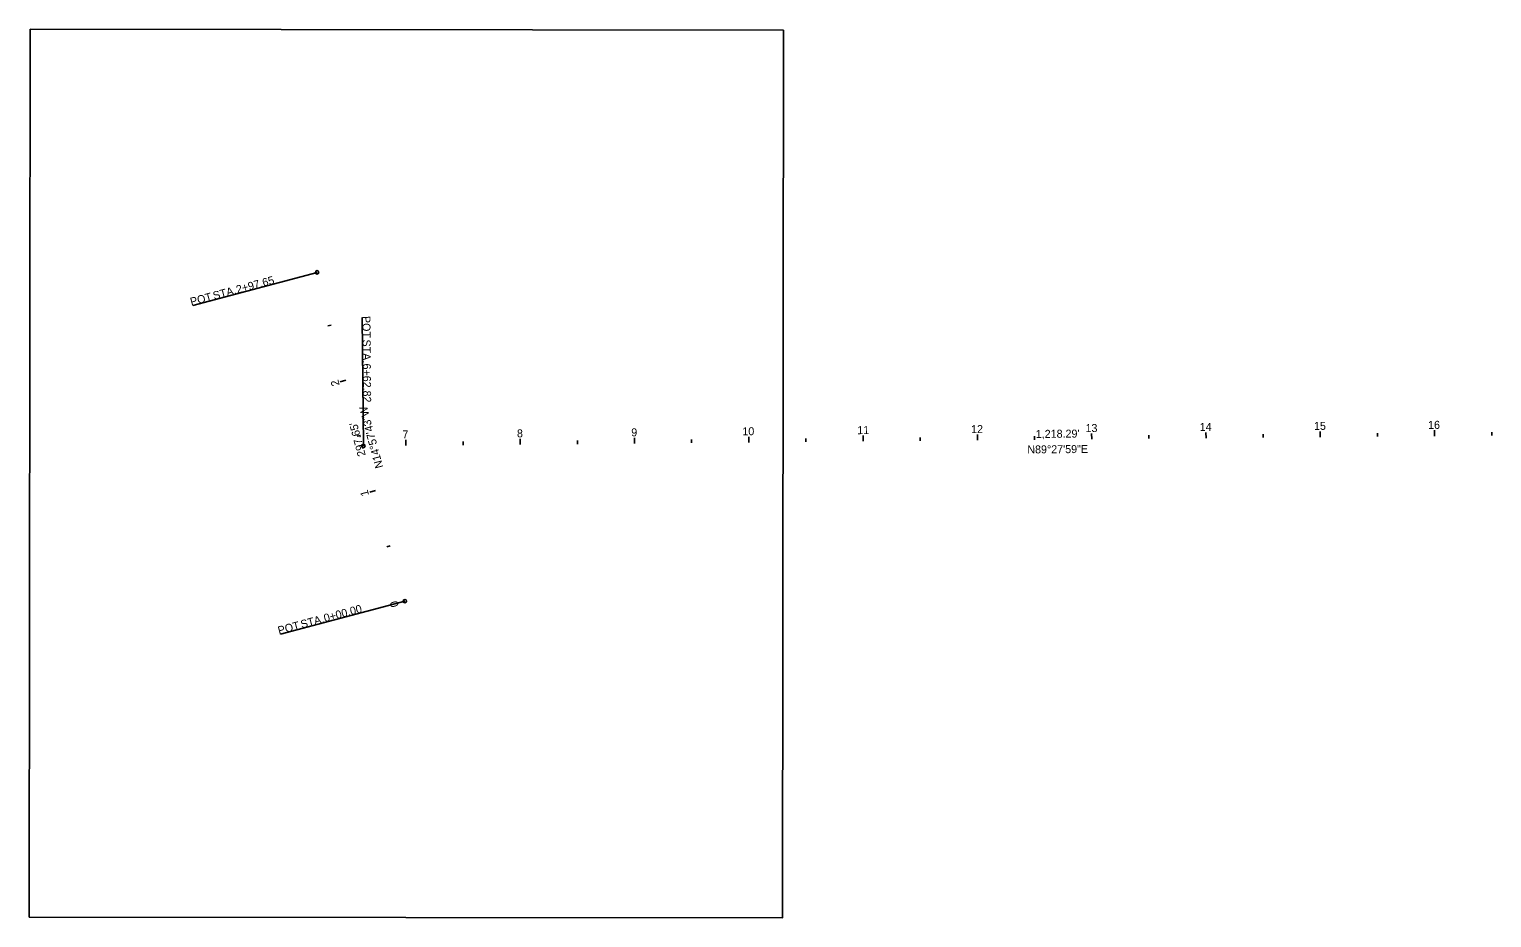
# Model space of a CAD drawing. Extents: x 1805035 to 1810276, y 297762 to 303660.
# Drawn here: x 1805035 to 1806314, y 297921 to 298699 of the extents above; entities that cross this region are included whole.
import ezdxf

# ---------------------------------------------------------------- set-up
doc = ezdxf.new("R2010")
doc.units = 0
for name, color, linetype in [('GE_P_Alignment_100_Bearings', 7, 'Continuous'), ('GE_P_Alignment_100_Cardinal_Points', 7, 'Continuous'), ('GE_P_Alignment_100_Distances', 7, 'Continuous'), ('GE_P_Alignment_100_Stations', 7, 'Continuous'), ('SH_Data', 7, 'Continuous')]:
    doc.layers.add(name, color=color, linetype=linetype)

msp = doc.modelspace()

# ---------------------------------------------------------------- linework, layer by layer
at = {"layer": 'GE_P_Alignment_100_Cardinal_Points'}
for p, q in [((1805286.6, 298486), (1805177.9, 298456.9)), ((1805327.1, 298334.1), (1805326.1, 298446.6)), ((1805363.4, 298198.4), (1805254.7, 298169.4))]:
    msp.add_line(p, q, dxfattribs=at)
for centre in [(1805286.6, 298486), (1805327.1, 298334.1), (1805363.4, 298198.4)]:
    msp.add_circle(centre, 1.5, dxfattribs=at)
at = {"layer": 'GE_P_Alignment_100_Stations'}
for p, q in [((1805298.9, 298439.9), (1805296, 298439.2)), ((1805311.8, 298391.6), (1805306.9, 298390.3)), ((1805324.7, 298343.3), (1805321.8, 298342.6)), ((1805664.3, 298337.2), (1805664.3, 298342.2)), ((1805764.3, 298338.2), (1805764.3, 298343.2)), ((1805814.3, 298338.6), (1805814.3, 298341.6)), ((1805864.3, 298339.1), (1805864.3, 298344.1)), ((1805914.3, 298339.6), (1805914.3, 298342.6)), ((1805964.3, 298340), (1805964.2, 298345)), ((1806014.3, 298340.5), (1806014.3, 298343.5)), ((1806064.3, 298341), (1806064.2, 298346)), ((1806114.3, 298341.4), (1806114.3, 298344.4)), ((1806164.3, 298341.9), (1806164.2, 298346.9)), ((1806214.3, 298342.4), (1806214.3, 298345.4)), ((1806264.3, 298342.8), (1806264.2, 298347.8)), ((1806314.3, 298343.3), (1806314.3, 298346.3)), ((1805364.3, 298334.4), (1805364.3, 298339.4)), ((1805414.3, 298334.9), (1805414.3, 298337.9)), ((1805464.3, 298335.4), (1805464.3, 298340.4)), ((1805514.3, 298335.8), (1805514.3, 298338.8)), ((1805564.3, 298336.3), (1805564.3, 298341.3)), ((1805614.3, 298336.8), (1805614.3, 298339.8)), ((1805714.3, 298337.7), (1805714.3, 298340.7)), ((1805337.6, 298295), (1805332.8, 298293.7)), ((1805350.5, 298246.7), (1805347.6, 298245.9)), ((1805363.4, 298198.4), (1805358.6, 298197.1))]:
    msp.add_line(p, q, dxfattribs=at)
at = {"layer": 'SH_Data'}
msp.add_lwpolyline([(1805694.7, 298698), (1805693.9, 297921.3), (1805034.8, 297922), (1805035.6, 298698.7)], close=True, dxfattribs=at)

# ---------------------------------------------------------------- texts
at = {"layer": 'GE_P_Alignment_100_Bearings'}
for s, rotation, p in [('N14°57\'43"W', 104.9619, (1805344.5, 298315.6)), ('N89°27\'59"E', 0.5335, (1805908, 298327.5))]:
    msp.add_text(s, height=7, rotation=rotation, dxfattribs=at).set_placement(p)
at = {"layer": 'GE_P_Alignment_100_Cardinal_Points'}
for s, rotation, p in [('2+97.65', 14.9619, (1805216.8, 298467.4)), (' STA. ', 14.9619, (1805194, 298461.3)), ('POT', 14.9619, (1805176.6, 298456.7)), ('POT', 270.5335, (1805326.2, 298447.8)), (' STA. ', 270.5335, (1805326.4, 298429.8)), ('6+62.82', 270.5335, (1805326.6, 298406.2)), ('0+00.00', 14.9619, (1805293.5, 298179.9)), ('POT', 14.9619, (1805253.3, 298169.1)), (' STA. ', 14.9619, (1805270.7, 298173.8))]:
    msp.add_text(s, height=7, rotation=rotation, dxfattribs=at).set_placement(p)
at = {"layer": 'GE_P_Alignment_100_Distances'}
for s, rotation, p in [("297.65'", 104.9619, (1805329.2, 298326)), ("1,218.29'", 0.5335, (1805915.4, 298341.1))]:
    msp.add_text(s, height=7, rotation=rotation, dxfattribs=at).set_placement(p)
at = {"layer": 'GE_P_Alignment_100_Stations'}
for s, rotation, p in [('2', 104.9619, (1805306.4, 298387.5)), ('14', 0.5335, (1806058.8, 298347.2)), ('15', 0.5335, (1806158.8, 298348.1)), ('16', 0.5335, (1806258.6, 298349)), ('7', 0.5335, (1805361.3, 298340.7)), ('8', 0.5335, (1805461.5, 298341.6)), ('9', 0.5335, (1805561.5, 298342.5)), ('10', 0.5335, (1805658.7, 298343.4)), ('11', 0.5335, (1805759.2, 298344.4)), ('12', 0.5335, (1805858.8, 298345.3)), ('13', 0.5335, (1805958.9, 298346.2)), ('1', 104.9619, (1805332.1, 298291.2)), ('0', 104.9619, (1805358.1, 298194.1))]:
    msp.add_text(s, height=7, rotation=rotation, dxfattribs=at).set_placement(p)

doc.saveas('drawing.dxf')
